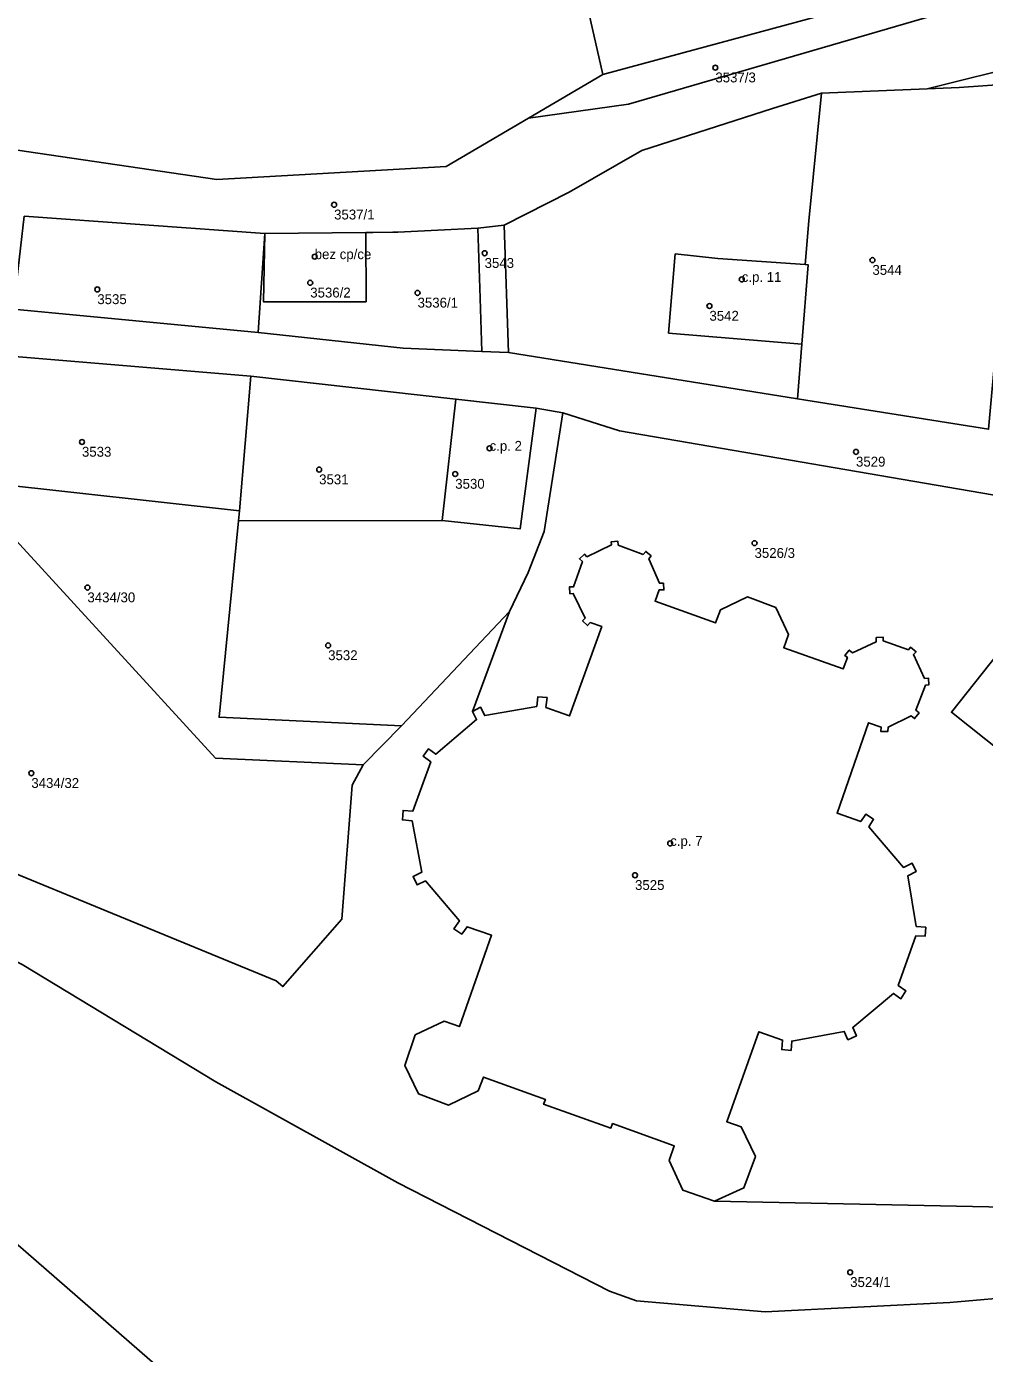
# Model space of a CAD drawing. Extents: x -878211 to -870363, y -1058464 to -1052522.
# Drawn here: x -876345.2 to -876248.4, y -1055057.5 to -1054923.3 of the extents above; entities that cross this region are included whole.
import ezdxf

# ---------------------------------------------------------------- set-up
doc = ezdxf.new("R2010")
doc.units = 0
for name, color, linetype in [('Vrstva 50', 7, 'Continuous'), ('Vrstva 51', 7, 'Continuous'), ('Vrstva 52', 7, 'Continuous')]:
    doc.layers.add(name, color=color, linetype=linetype)

msp = doc.modelspace()

# ---------------------------------------------------------------- linework, layer by layer
at = {"layer": 'Vrstva 50'}
for centre in [(-876275.58, -1054927.46994), (-876314.13, -1054941.32994), (-876316.09, -1054946.57994), (-876298.91, -1054946.22994), (-876259.7, -1054946.92994), (-876316.54, -1054949.21994), (-876272.91, -1054948.87994), (-876338.07, -1054949.88994), (-876305.69, -1054950.23994), (-876276.18, -1054951.56994), (-876339.62, -1054965.31994), (-876298.41, -1054965.95994), (-876261.36, -1054966.31994), (-876315.64, -1054968.10994), (-876301.88, -1054968.55994), (-876271.62, -1054975.54994), (-876339.07, -1054980.03994), (-876314.73, -1054985.88994), (-876344.74, -1054998.80994), (-876280.15, -1055005.90994), (-876283.7, -1055009.12994), (-876261.95, -1055049.27994)]:
    msp.add_circle(centre, 0.25, dxfattribs=at)
at = {"layer": 'Vrstva 51'}
for points in [[(-876385.33, -1054930.06), (-876351.91, -1054934.98), (-876325.98, -1054938.79), (-876302.79, -1054937.47), (-876294.48, -1054932.58), (-876286.97, -1054928.17), (-876291.78, -1054906.9), (-876297.96, -1054890.06), (-876299.88, -1054875.09), (-876309.04, -1054869.25), (-876318.21, -1054867.84), (-876339.28, -1054874.2), (-876356, -1054887.75), (-876380.69, -1054897.58), (-876399.9, -1054901.85), (-876408.73, -1054905.38), (-876418.87, -1054910.9), (-876423.48, -1054914.13), (-876427.47, -1054915.93), (-876428.71, -1054917.43), (-876423.95, -1054924.24), (-876403.1, -1054932.35)], [(-876245.21, -1054919.74), (-876243.34, -1054905.33), (-876262.86, -1054909.66), (-876291.78, -1054906.9), (-876286.97, -1054928.17), (-876264.63, -1054922.12)], [(-876245.21, -1054919.74), (-876264.63, -1054922.12), (-876286.97, -1054928.17), (-876294.48, -1054932.58), (-876284.35, -1054931.17)], [(-876243.27, -1054928.94), (-876226.91, -1054926.9), (-876243.87, -1054927.05), (-876254.17, -1054929.61), (-876250.92, -1054929.47)], [(-876250.92, -1054929.47), (-876254.17, -1054929.61), (-876264.85, -1054930.05), (-876266.13, -1054942.96), (-876266.5, -1054947.38), (-876266.2, -1054947.4), (-876266.83, -1054955.43), (-876267.26, -1054960.95), (-876247.95, -1054964.03), (-876247.29, -1054956.62), (-876245.27, -1054933.93), (-876243.38, -1054933.76), (-876243.27, -1054928.94)], [(-876264.85, -1054930.05), (-876269.8, -1054931.6), (-876283.01, -1054935.86), (-876290.37, -1054940.07), (-876296.94, -1054943.38), (-876296.49, -1054956.28), (-876267.26, -1054960.95), (-876266.83, -1054955.43), (-876266.2, -1054947.4), (-876266.5, -1054947.38), (-876266.13, -1054942.96)], [(-876321.8, -1054954.26), (-876321.14, -1054944.23), (-876345.46, -1054942.49), (-876345.83, -1054945.71), (-876346.55, -1054951.9)], [(-876321.25, -1054951.15), (-876321.14, -1054944.23), (-876321.8, -1054954.26), (-876307.13, -1054955.82), (-876299.2, -1054956.16), (-876299.37, -1054950.78), (-876299.59, -1054943.69), (-876307.7, -1054944.11), (-876308.2, -1054944.11), (-876310.2, -1054944.13), (-876310.92, -1054944.14), (-876310.9, -1054951.14)], [(-876310.92, -1054944.14), (-876321.14, -1054944.23), (-876321.25, -1054951.15), (-876310.9, -1054951.14)], [(-876299.37, -1054950.78), (-876299.2, -1054956.16), (-876296.49, -1054956.28), (-876296.94, -1054943.38), (-876299.59, -1054943.69)], [(-876323.7, -1054972.29), (-876322.54, -1054958.67), (-876347.21, -1054956.62), (-876348.7, -1054969.52)], [(-876303.2, -1054973.25), (-876301.81, -1054960.98), (-876322.54, -1054958.67), (-876323.7, -1054972.29), (-876323.78, -1054973.29)], [(-876303.2, -1054973.25), (-876295.3, -1054974.1), (-876293.7, -1054961.9), (-876301.81, -1054960.98)], [(-876323.78, -1054973.29), (-876325.75, -1054993.15), (-876307.31, -1054994.01), (-876296.41, -1054982.45), (-876294.52, -1054978.5), (-876292.89, -1054974.37), (-876291.01, -1054962.38), (-876293.7, -1054961.9), (-876295.3, -1054974.1), (-876303.2, -1054973.25)], [(-876348.7, -1054969.52), (-876366.72, -1055000.87), (-876364.74, -1055001.39), (-876319.98, -1055019.81), (-876319.3, -1055020.38), (-876313.33, -1055013.57), (-876312.3, -1055000.03), (-876311.19, -1054997.97), (-876326.11, -1054997.28), (-876348.87, -1054972.47)], [(-876323.78, -1054973.29), (-876323.7, -1054972.29), (-876348.7, -1054969.52), (-876348.87, -1054972.47), (-876326.11, -1054997.28), (-876311.19, -1054997.97), (-876307.31, -1054994.01), (-876325.75, -1054993.15)], [(-876230.61, -1055019.14), (-876225.89, -1055023.06), (-876221.26, -1055017.49), (-876216.66, -1055021.3), (-876202.64, -1055032.79), (-876197.32, -1055029.35), (-876182.5, -1055017.11), (-876202.1, -1055003.26), (-876211.84, -1054995.38), (-876218.33, -1054990.08), (-876212.05, -1054982.01), (-876236.87, -1054973.88), (-876237.48, -1054974.65), (-876245.51, -1054984.81), (-876251.72, -1054992.65), (-876242.95, -1054999.62), (-876226.09, -1055013.5)], [(-876316.66, -1055102.83), (-876306.38, -1055081.71), (-876323.34, -1055066.32), (-876358.9, -1055035.38), (-876377.75, -1055027.25), (-876396.33, -1055052.17), (-876351.9, -1055057.99), (-876356.57, -1055092.43), (-876334.52, -1055096.3)]]:
    msp.add_lwpolyline(points, close=True, dxfattribs=at)
for points in [[(-876245.21, -1054919.74), (-876284.35, -1054931.17), (-876294.48, -1054932.58), (-876302.79, -1054937.47), (-876325.98, -1054938.79), (-876351.91, -1054934.98)], [(-876345.46, -1054942.49), (-876321.14, -1054944.23), (-876310.92, -1054944.14), (-876310.2, -1054944.13), (-876308.2, -1054944.11), (-876307.7, -1054944.11), (-876299.59, -1054943.69), (-876296.94, -1054943.38), (-876290.37, -1054940.07), (-876283.01, -1054935.86), (-876269.8, -1054931.6), (-876264.85, -1054930.05), (-876254.17, -1054929.61), (-876243.87, -1054927.05)], [(-876247.95, -1054964.03), (-876267.26, -1054960.95), (-876296.49, -1054956.28), (-876299.2, -1054956.16), (-876307.13, -1054955.82), (-876321.8, -1054954.26), (-876346.55, -1054951.9), (-876347.21, -1054956.62), (-876322.54, -1054958.67), (-876301.81, -1054960.98), (-876293.7, -1054961.9), (-876291.01, -1054962.38), (-876285.26, -1054964.19), (-876245.2, -1054971.07)], [(-876245.2, -1054971.07), (-876285.26, -1054964.19), (-876291.01, -1054962.38), (-876292.89, -1054974.37), (-876294.52, -1054978.5), (-876296.41, -1054982.45), (-876300.15, -1054992.56), (-876299.31, -1054992.14), (-876298.89, -1054992.98), (-876293.64, -1054992.05), (-876293.54, -1054991.09), (-876292.6, -1054991.17), (-876292.71, -1054992.16), (-876290.32, -1054993.02), (-876287.06, -1054983.99), (-876288.24, -1054983.58), (-876288.51, -1054983.88), (-876289, -1054983.39), (-876288.73, -1054983.12), (-876289.95, -1054980.65), (-876290.29, -1054980.67), (-876290.33, -1054979.98), (-876289.94, -1054979.98), (-876289.03, -1054977.42), (-876289.32, -1054977.12), (-876288.82, -1054976.66), (-876288.56, -1054976.92), (-876286.09, -1054975.72), (-876286.11, -1054975.4), (-876285.44, -1054975.36), (-876285.4, -1054975.74), (-876282.87, -1054976.68), (-876282.62, -1054976.38), (-876282.08, -1054976.84), (-876282.32, -1054977.13), (-876281.22, -1054979.6), (-876280.84, -1054979.6), (-876280.78, -1054980.27), (-876281.27, -1054980.27), (-876281.68, -1054981.4), (-876275.55, -1054983.62), (-876275.07, -1054982.3), (-876272.32, -1054980.96), (-876269.48, -1054982.06), (-876268.18, -1054984.8), (-876268.67, -1054986.13), (-876262.67, -1054988.27), (-876262.23, -1054987.11), (-876262.5, -1054986.9), (-876262.05, -1054986.36), (-876261.73, -1054986.65), (-876259.32, -1054985.52), (-876259.32, -1054985.09), (-876258.62, -1054985.05), (-876258.61, -1054985.43), (-876256.06, -1054986.33), (-876255.84, -1054986.05), (-876255.28, -1054986.53), (-876255.55, -1054986.82), (-876254.43, -1054989.22), (-876254.04, -1054989.2), (-876254, -1054989.89), (-876254.35, -1054989.92), (-876255.3, -1054992.45), (-876254.98, -1054992.71), (-876255.44, -1054993.28), (-876255.77, -1054993.02), (-876258.12, -1054994.16), (-876258.13, -1054994.59), (-876258.86, -1054994.58), (-876258.83, -1054994.14), (-876260.09, -1054993.71), (-876263.27, -1055002.86), (-876260.88, -1055003.71), (-876260.36, -1055002.95), (-876259.58, -1055003.47), (-876260.08, -1055004.25), (-876256.57, -1055008.34), (-876255.69, -1055007.9), (-876255.27, -1055008.75), (-876256.11, -1055009.18), (-876255.27, -1055014.3), (-876254.31, -1055014.39), (-876254.38, -1055015.3), (-876255.31, -1055015.26), (-876257.09, -1055020.28), (-876256.31, -1055020.82), (-876256.82, -1055021.61), (-876257.58, -1055021.07), (-876261.69, -1055024.52)], [(-876280.84, -1054979.6), (-876281.22, -1054979.6), (-876282.32, -1054977.13), (-876282.08, -1054976.84), (-876282.62, -1054976.38), (-876282.87, -1054976.68), (-876285.4, -1054975.74), (-876285.44, -1054975.36), (-876286.11, -1054975.4), (-876286.09, -1054975.72), (-876288.56, -1054976.92), (-876288.82, -1054976.66), (-876289.32, -1054977.12), (-876289.03, -1054977.42), (-876289.94, -1054979.98), (-876290.33, -1054979.98), (-876290.29, -1054980.67), (-876289.95, -1054980.65), (-876288.73, -1054983.12), (-876289, -1054983.39), (-876288.51, -1054983.88), (-876288.24, -1054983.58), (-876287.06, -1054983.99), (-876290.32, -1054993.02), (-876292.71, -1054992.16), (-876292.6, -1054991.17), (-876293.54, -1054991.09), (-876293.64, -1054992.05), (-876298.89, -1054992.98), (-876299.31, -1054992.14), (-876300.15, -1054992.56)], [(-876300.15, -1054992.56), (-876299.72, -1054993.39), (-876303.83, -1054996.89), (-876304.57, -1054996.34), (-876305.12, -1054997.09), (-876304.36, -1054997.65), (-876306.18, -1055002.65), (-876307.15, -1055002.58), (-876307.22, -1055003.54), (-876306.24, -1055003.61), (-876305.27, -1055008.83), (-876306.15, -1055009.24), (-876305.74, -1055010.11), (-876304.89, -1055009.7), (-876301.46, -1055013.74), (-876302.01, -1055014.56), (-876301.22, -1055015.08), (-876300.69, -1055014.33), (-876298.21, -1055015.2), (-876301.45, -1055024.43), (-876302.99, -1055023.89), (-876305.92, -1055025.28), (-876306.98, -1055028.35), (-876305.58, -1055031.24), (-876302.56, -1055032.37), (-876299.57, -1055030.93), (-876299.03, -1055029.53), (-876292.76, -1055031.79), (-876292.94, -1055032.29), (-876286.14, -1055034.7), (-876285.98, -1055034.24), (-876279.73, -1055036.5), (-876280.25, -1055037.96), (-876278.88, -1055040.97), (-876275.67, -1055042.1), (-876272.69, -1055040.72), (-876271.53, -1055037.57), (-876272.96, -1055034.57), (-876274.43, -1055034.05), (-876271.2, -1055024.96), (-876268.78, -1055025.79), (-876268.87, -1055026.75), (-876267.92, -1055026.84), (-876267.86, -1055025.9), (-876262.55, -1055024.92), (-876262.17, -1055025.76), (-876261.32, -1055025.37), (-876261.69, -1055024.52), (-876257.58, -1055021.07), (-876256.82, -1055021.61), (-876256.31, -1055020.82), (-876257.09, -1055020.28), (-876255.31, -1055015.26), (-876254.38, -1055015.3), (-876254.31, -1055014.39), (-876255.27, -1055014.3), (-876256.11, -1055009.18), (-876255.27, -1055008.75), (-876255.69, -1055007.9), (-876256.57, -1055008.34), (-876260.08, -1055004.25), (-876259.58, -1055003.47), (-876260.36, -1055002.95), (-876260.88, -1055003.71), (-876263.27, -1055002.86), (-876260.09, -1054993.71), (-876258.83, -1054994.14), (-876258.86, -1054994.58), (-876258.13, -1054994.59), (-876258.12, -1054994.16), (-876255.77, -1054993.02), (-876255.44, -1054993.28), (-876254.98, -1054992.71), (-876255.3, -1054992.45), (-876254.35, -1054989.92), (-876254, -1054989.89), (-876254.04, -1054989.2), (-876254.43, -1054989.22), (-876255.55, -1054986.82), (-876255.28, -1054986.53), (-876255.84, -1054986.05), (-876256.06, -1054986.33), (-876258.61, -1054985.43), (-876258.62, -1054985.05), (-876259.32, -1054985.09), (-876259.32, -1054985.52), (-876261.73, -1054986.65), (-876262.05, -1054986.36), (-876262.5, -1054986.9), (-876262.23, -1054987.11), (-876262.67, -1054988.27), (-876268.67, -1054986.13), (-876268.18, -1054984.8), (-876269.48, -1054982.06), (-876272.32, -1054980.96), (-876275.07, -1054982.3), (-876275.55, -1054983.62), (-876281.68, -1054981.4), (-876281.27, -1054980.27), (-876280.78, -1054980.27), (-876280.84, -1054979.6)], [(-876243.04, -1055042.76), (-876275.67, -1055042.1), (-876278.88, -1055040.97), (-876280.25, -1055037.96), (-876279.73, -1055036.5), (-876285.98, -1055034.24), (-876286.14, -1055034.7), (-876292.94, -1055032.29), (-876292.76, -1055031.79), (-876299.03, -1055029.53), (-876299.57, -1055030.93), (-876302.56, -1055032.37), (-876305.58, -1055031.24), (-876306.98, -1055028.35), (-876305.92, -1055025.28), (-876302.99, -1055023.89), (-876301.45, -1055024.43), (-876298.21, -1055015.2), (-876300.69, -1055014.33), (-876301.22, -1055015.08), (-876302.01, -1055014.56), (-876301.46, -1055013.74), (-876304.89, -1055009.7), (-876305.74, -1055010.11), (-876306.15, -1055009.24), (-876305.27, -1055008.83), (-876306.24, -1055003.61), (-876307.22, -1055003.54), (-876307.15, -1055002.58), (-876306.18, -1055002.65), (-876304.36, -1054997.65), (-876305.12, -1054997.09), (-876304.57, -1054996.34), (-876303.83, -1054996.89), (-876299.72, -1054993.39), (-876300.15, -1054992.56), (-876296.41, -1054982.45), (-876307.31, -1054994.01), (-876311.19, -1054997.97), (-876312.3, -1055000.03), (-876313.33, -1055013.57), (-876319.3, -1055020.38), (-876319.98, -1055019.81), (-876364.74, -1055001.39)], [(-876242.95, -1054999.62), (-876251.72, -1054992.65), (-876245.51, -1054984.81)], [(-876236.43, -1055051), (-876251.86, -1055052.34), (-876270.53, -1055053.27), (-876283.55, -1055052.17), (-876286.3, -1055051.17), (-876307.7, -1055040.24), (-876326.07, -1055030.03), (-876345.67, -1055018.17), (-876361.59, -1055010.4), (-876366.45, -1055010.72), (-876368.57, -1055011.46), (-876377.75, -1055027.25), (-876358.9, -1055035.38), (-876323.34, -1055066.32), (-876306.38, -1055081.71), (-876316.66, -1055102.83), (-876314.44, -1055103.64), (-876294.05, -1055111.65), (-876279.48, -1055115.89), (-876264.87, -1055113.38), (-876253.17, -1055110.11), (-876221.24, -1055096.79)], [(-876345.67, -1055018.17), (-876326.07, -1055030.03), (-876307.7, -1055040.24), (-876286.3, -1055051.17), (-876283.55, -1055052.17), (-876270.53, -1055053.27), (-876251.86, -1055052.34), (-876236.43, -1055051)], [(-876261.69, -1055024.52), (-876261.32, -1055025.37), (-876262.17, -1055025.76), (-876262.55, -1055024.92), (-876267.86, -1055025.9), (-876267.92, -1055026.84), (-876268.87, -1055026.75), (-876268.78, -1055025.79), (-876271.2, -1055024.96), (-876274.43, -1055034.05), (-876272.96, -1055034.57)], [(-876272.96, -1055034.57), (-876271.53, -1055037.57), (-876272.69, -1055040.72), (-876275.67, -1055042.1), (-876243.04, -1055042.76)]]:
    msp.add_lwpolyline(points, dxfattribs=at)
at = {"layer": 'Vrstva 52'}
for points in [[(-876321.14, -1054944.23), (-876321.25, -1054951.15), (-876310.9, -1054951.14), (-876310.92, -1054944.14)], [(-876280.32, -1054954.31), (-876266.83, -1054955.43), (-876266.2, -1054947.4), (-876266.5, -1054947.38), (-876275.33, -1054946.75), (-876279.63, -1054946.3)], [(-876293.7, -1054961.9), (-876301.81, -1054960.98), (-876303.2, -1054973.25), (-876295.3, -1054974.1)]]:
    msp.add_lwpolyline(points, close=True, dxfattribs=at)
for points in [[(-876274.43, -1055034.05), (-876271.2, -1055024.96), (-876268.78, -1055025.79), (-876268.87, -1055026.75), (-876267.92, -1055026.84), (-876267.86, -1055025.9), (-876262.55, -1055024.92), (-876262.17, -1055025.76), (-876261.32, -1055025.37), (-876261.69, -1055024.52), (-876257.58, -1055021.07), (-876256.82, -1055021.61), (-876256.31, -1055020.82), (-876257.09, -1055020.28), (-876255.31, -1055015.26), (-876254.38, -1055015.3), (-876254.31, -1055014.39), (-876255.27, -1055014.3), (-876256.11, -1055009.18), (-876255.27, -1055008.75), (-876255.69, -1055007.9), (-876256.57, -1055008.34), (-876260.08, -1055004.25), (-876259.58, -1055003.47), (-876260.36, -1055002.95), (-876260.88, -1055003.71), (-876263.27, -1055002.86), (-876260.09, -1054993.71), (-876258.83, -1054994.14), (-876258.86, -1054994.58), (-876258.13, -1054994.59), (-876258.12, -1054994.16), (-876255.77, -1054993.02), (-876255.44, -1054993.28), (-876254.98, -1054992.71), (-876255.3, -1054992.45), (-876254.35, -1054989.92), (-876254, -1054989.89), (-876254.04, -1054989.2), (-876254.43, -1054989.22), (-876255.55, -1054986.82), (-876255.28, -1054986.53), (-876255.84, -1054986.05), (-876256.06, -1054986.33), (-876258.61, -1054985.43), (-876258.62, -1054985.05), (-876259.32, -1054985.09), (-876259.32, -1054985.52), (-876261.73, -1054986.65), (-876262.05, -1054986.36), (-876262.5, -1054986.9), (-876262.23, -1054987.11), (-876262.67, -1054988.27), (-876268.67, -1054986.13), (-876268.18, -1054984.8), (-876269.48, -1054982.06), (-876272.32, -1054980.96), (-876275.07, -1054982.3), (-876275.55, -1054983.62), (-876281.68, -1054981.4), (-876281.27, -1054980.27), (-876280.78, -1054980.27), (-876280.84, -1054979.6), (-876281.22, -1054979.6), (-876282.32, -1054977.13), (-876282.08, -1054976.84), (-876282.62, -1054976.38), (-876282.87, -1054976.68), (-876285.4, -1054975.74), (-876285.44, -1054975.36), (-876286.11, -1054975.4), (-876286.09, -1054975.72), (-876288.56, -1054976.92), (-876288.82, -1054976.66), (-876289.32, -1054977.12), (-876289.03, -1054977.42), (-876289.94, -1054979.98), (-876290.33, -1054979.98), (-876290.29, -1054980.67), (-876289.95, -1054980.65), (-876288.73, -1054983.12), (-876289, -1054983.39), (-876288.51, -1054983.88), (-876288.24, -1054983.58), (-876287.06, -1054983.99), (-876290.32, -1054993.02), (-876292.71, -1054992.16), (-876292.6, -1054991.17), (-876293.54, -1054991.09), (-876293.64, -1054992.05), (-876298.89, -1054992.98), (-876299.31, -1054992.14), (-876300.15, -1054992.56), (-876299.72, -1054993.39), (-876303.83, -1054996.89), (-876304.57, -1054996.34), (-876305.12, -1054997.09), (-876304.36, -1054997.65), (-876306.18, -1055002.65), (-876307.15, -1055002.58), (-876307.22, -1055003.54)], [(-876307.22, -1055003.54), (-876306.24, -1055003.61), (-876305.27, -1055008.83), (-876306.15, -1055009.24), (-876305.74, -1055010.11), (-876304.89, -1055009.7), (-876301.46, -1055013.74), (-876302.01, -1055014.56), (-876301.22, -1055015.08), (-876300.69, -1055014.33), (-876298.21, -1055015.2), (-876301.45, -1055024.43), (-876302.99, -1055023.89), (-876305.92, -1055025.28), (-876306.98, -1055028.35), (-876305.58, -1055031.24), (-876302.56, -1055032.37), (-876299.57, -1055030.93), (-876299.03, -1055029.53), (-876292.76, -1055031.79), (-876292.94, -1055032.29), (-876286.14, -1055034.7), (-876285.98, -1055034.24), (-876279.73, -1055036.5), (-876280.25, -1055037.96), (-876278.88, -1055040.97), (-876275.67, -1055042.1), (-876272.69, -1055040.72), (-876271.53, -1055037.57), (-876272.96, -1055034.57), (-876274.43, -1055034.05)]]:
    msp.add_lwpolyline(points, dxfattribs=at)

# ---------------------------------------------------------------- texts
at = {"layer": 'Vrstva 50'}
for s, p in [('3537/3', (-876275.58, -1054928.959)), ('3537/1', (-876314.13, -1054942.819)), ('bez cp/ce', (-876316.09, -1054946.83)), ('3543', (-876298.91, -1054947.719)), ('c.p. 11', (-876272.91, -1054949.129)), ('3544', (-876259.7, -1054948.419)), ('3535', (-876338.07, -1054951.379)), ('3536/2', (-876316.54, -1054950.709)), ('3536/1', (-876305.69, -1054951.729)), ('3542', (-876276.18, -1054953.059)), ('c.p. 2', (-876298.41, -1054966.21)), ('3533', (-876339.62, -1054966.809)), ('3529', (-876261.36, -1054967.809)), ('3531', (-876315.64, -1054969.599)), ('3530', (-876301.88, -1054970.049)), ('3526/3', (-876271.62, -1054977.039)), ('3434/30', (-876339.07, -1054981.529)), ('3532', (-876314.73, -1054987.379)), ('3434/32', (-876344.74, -1055000.299)), ('c.p. 7', (-876280.15, -1055006.159)), ('3525', (-876283.7, -1055010.619)), ('3524/1', (-876261.95, -1055050.769))]:
    msp.add_text(s, height=0.999996, dxfattribs=at).set_placement(p)

doc.saveas('drawing.dxf')
